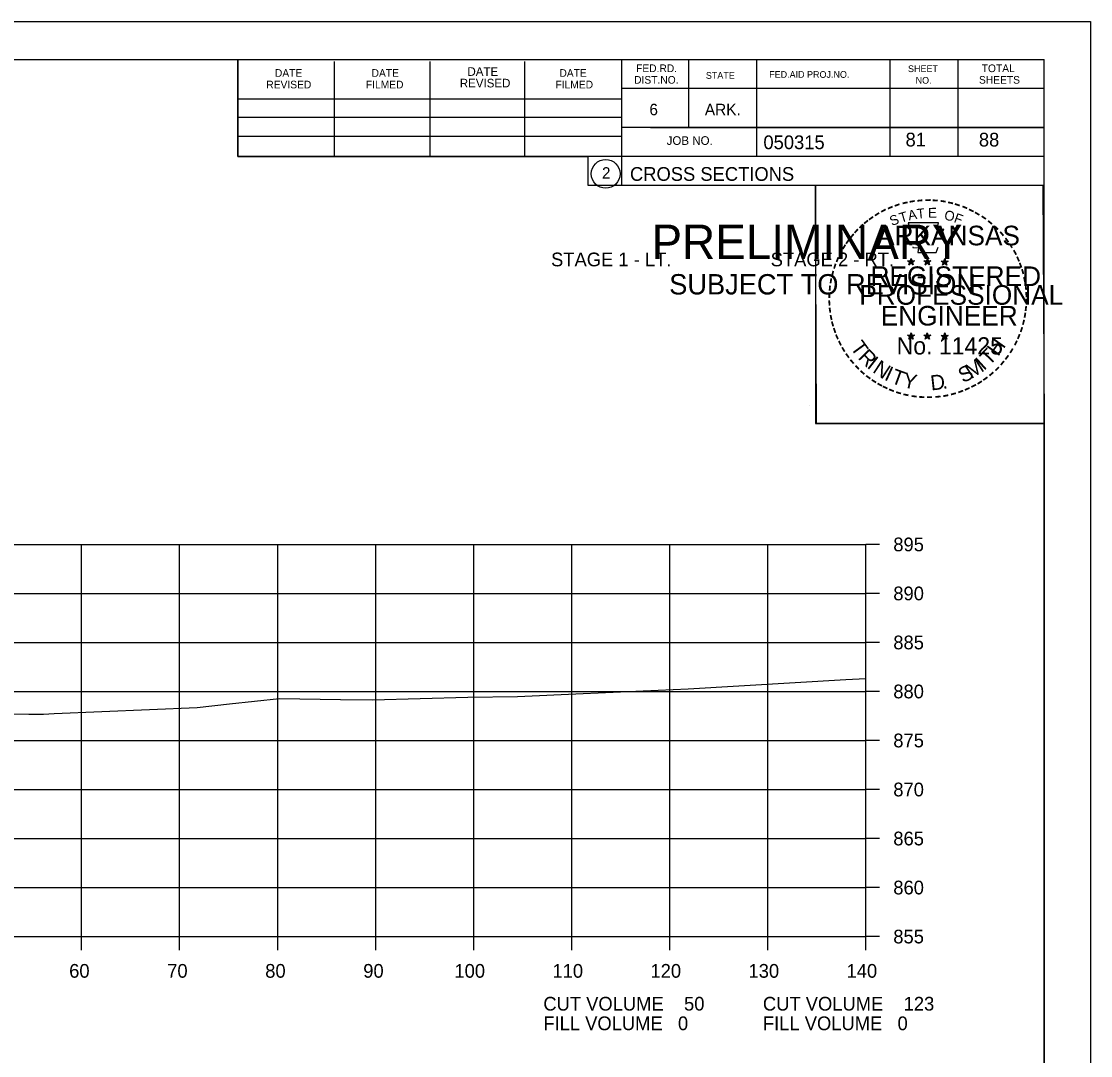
# Model space of a CAD drawing. Extents: x 1486524 to 1499135, y 326561 to 337924.
# Drawn here: x 1489036.7 to 1489145.8, y 334807.2 to 334912.7 of the extents above; entities that cross this region are included whole.
import ezdxf

# ---------------------------------------------------------------- set-up
doc = ezdxf.new("R2010")
doc.units = 0
for name, color, linetype in [('Default', 7, 'Continuous'), ('E_Const Align', 7, 'Continuous'), ('E_Const Align Station', 7, 'Continuous'), ('E_Ownership Information', 7, 'Continuous'), ('E_Property Line', 7, 'Continuous'), ('E_Quarter Calls', 7, 'Continuous'), ('E_Section Line', 7, 'Continuous'), ('E_Station Offset', 7, 'Continuous'), ('E_Tract Number', 7, 'Continuous'), ('S_SIXTEEN_SECTION', 7, 'Continuous')]:
    doc.layers.add(name, color=color, linetype=linetype)

msp = doc.modelspace()

# ---------------------------------------------------------------- linework, layer by layer
at = {"layer": 'E_Const Align'}
for p, q in [((1489122.89, 334819.33), (1489122.89, 334859.33)), ((1489124.29, 334859.33), (1489122.89, 334859.33)), ((1489124.29, 334854.33), (1489122.89, 334854.33)), ((1489124.29, 334849.33), (1489122.89, 334849.33)), ((1489124.29, 334844.33), (1489122.89, 334844.33)), ((1489124.29, 334839.33), (1489122.89, 334839.33)), ((1489124.29, 334834.33), (1489122.89, 334834.33)), ((1489124.29, 334829.33), (1489122.89, 334829.33)), ((1489124.29, 334824.33), (1489122.89, 334824.33)), ((1488842.89, 334819.33), (1489122.89, 334819.33)), ((1489042.89, 334817.93), (1489042.89, 334819.33)), ((1489052.89, 334817.93), (1489052.89, 334819.33)), ((1489062.89, 334817.93), (1489062.89, 334819.33)), ((1489072.89, 334817.93), (1489072.89, 334819.33)), ((1489082.89, 334817.93), (1489082.89, 334819.33)), ((1489092.89, 334817.93), (1489092.89, 334819.33)), ((1489102.89, 334817.93), (1489102.89, 334819.33)), ((1489112.89, 334817.93), (1489112.89, 334819.33)), ((1489122.89, 334817.93), (1489122.89, 334819.33)), ((1489124.29, 334819.33), (1489122.89, 334819.33))]:
    msp.add_line(p, q, dxfattribs=at)
at = {"layer": 'E_Ownership Information'}
for p, q in [((1488842.89, 334859.33), (1489122.89, 334859.33)), ((1489042.89, 334819.33), (1489042.89, 334859.33)), ((1489052.89, 334819.33), (1489052.89, 334859.33)), ((1489062.89, 334819.33), (1489062.89, 334859.33)), ((1489072.89, 334819.33), (1489072.89, 334859.33)), ((1489082.89, 334819.33), (1489082.89, 334859.33)), ((1489092.89, 334819.33), (1489092.89, 334859.33)), ((1489102.89, 334819.33), (1489102.89, 334859.33)), ((1489112.89, 334819.33), (1489112.89, 334859.33)), ((1489122.89, 334819.33), (1489122.89, 334859.33)), ((1488842.89, 334854.33), (1489122.89, 334854.33)), ((1488842.89, 334849.33), (1489122.89, 334849.33)), ((1488842.89, 334844.33), (1489122.89, 334844.33)), ((1488842.89, 334839.33), (1489122.89, 334839.33)), ((1488842.89, 334834.33), (1489122.89, 334834.33)), ((1488842.89, 334829.33), (1489122.89, 334829.33)), ((1488842.89, 334824.33), (1489122.89, 334824.33)), ((1488842.89, 334819.33), (1489122.89, 334819.33))]:
    msp.add_line(p, q, dxfattribs=at)
at = {"layer": 'E_Property Line'}
for p, q in [((1488824.89, 334908.79), (1489141.07, 334908.79)), ((1489058.81, 334898.91), (1489058.81, 334908.79)), ((1489068.67, 334898.91), (1489068.67, 334908.59)), ((1489078.43, 334898.91), (1489078.43, 334908.59)), ((1489088.11, 334898.91), (1489088.11, 334908.59)), ((1489097.97, 334908.79), (1489097.97, 334895.99)), ((1489104.81, 334908.79), (1489104.81, 334901.85)), ((1489111.75, 334908.79), (1489111.75, 334898.91)), ((1489125.33, 334908.79), (1489125.33, 334898.91)), ((1489132.27, 334908.79), (1489132.27, 334898.91)), ((1489141.07, 334703.33), (1489141.07, 334908.79)), ((1489141.07, 334905.85), (1489097.97, 334905.85)), ((1489141.07, 334905.87), (1489141.07, 334905.87)), ((1489058.81, 334904.77), (1489097.97, 334904.77)), ((1489058.81, 334902.91), (1489097.97, 334902.91)), ((1489141.07, 334901.85), (1489097.97, 334901.85)), ((1489100.93, 334901.85), (1489141.07, 334901.85)), ((1489058.81, 334898.91), (1489058.81, 334900.97)), ((1489058.81, 334900.97), (1489097.97, 334900.97)), ((1489141.07, 334898.91), (1489058.81, 334898.91)), ((1489097.97, 334895.99), (1489141.07, 334895.99))]:
    msp.add_line(p, q, dxfattribs=at)
msp.add_circle((1489096.35, 334897.13), 1.47, dxfattribs=at)
at = {"layer": 'E_Quarter Calls'}
for p, q in [((1488812.48, 334912.69), (1489145.82, 334912.69)), ((1489117.1, 334873.54), (1489117.1, 334873.54))]:
    msp.add_line(p, q, dxfattribs=at)
for points in [[(1488812.48, 334912.69), (1489145.82, 334912.69), (1489145.82, 334699.35), (1488812.48, 334699.35)], [(1489058.81, 334908.79), (1489058.81, 334898.91), (1489094.54, 334898.91), (1489094.54, 334895.99), (1489117.74, 334895.99), (1489117.74, 334871.66), (1489141.07, 334871.66), (1489141.07, 334703.33), (1488824.89, 334703.33), (1488824.89, 334908.79)], [(1489117.74, 334895.99), (1489140.94, 334895.99), (1489141.07, 334871.66), (1489117.86, 334871.66)]]:
    msp.add_lwpolyline(points, close=True, dxfattribs=at)
at = {"layer": 'E_Tract Number'}
msp.add_lwpolyline([(1489027.66, 334842.05), (1489037.52, 334842.02), (1489039.01, 334842.01), (1489040.08, 334842.07), (1489054.69, 334842.7), (1489057.97, 334843.07), (1489063.08, 334843.62), (1489069.29, 334843.52), (1489072.57, 334843.49), (1489082.3, 334843.74), (1489087.36, 334843.83), (1489094.07, 334844.13), (1489104.78, 334844.6), (1489120.86, 334845.55), (1489122.89, 334845.67)], dxfattribs=at)
at = {"layer": 'S_SIXTEEN_SECTION'}
for p, q in [((1489127.15, 334888.25), (1489127.5, 334888.14)), ((1489127.15, 334888.25), (1489127.4, 334888.2)), ((1489127.15, 334888.25), (1489127.39, 334888.12)), ((1489127.5, 334888.5), (1489127.46, 334888.25)), ((1489127.5, 334888.14), (1489127.5, 334888.5)), ((1489127.5, 334888.5), (1489127.55, 334888.25)), ((1489127.85, 334888.25), (1489127.5, 334888.14)), ((1489127.85, 334888.25), (1489127.56, 334888.2)), ((1489127.85, 334888.25), (1489127.64, 334888.14)), ((1489128.82, 334888.25), (1489129.17, 334888.14)), ((1489128.82, 334888.25), (1489129.07, 334888.2)), ((1489128.82, 334888.25), (1489129.06, 334888.12)), ((1489129.17, 334888.5), (1489129.13, 334888.25)), ((1489129.17, 334888.14), (1489129.17, 334888.5)), ((1489129.17, 334888.5), (1489129.22, 334888.25)), ((1489129.52, 334888.25), (1489129.17, 334888.14)), ((1489129.52, 334888.25), (1489129.23, 334888.2)), ((1489129.52, 334888.25), (1489129.31, 334888.14)), ((1489130.93, 334888.49), (1489130.89, 334888.24)), ((1489130.93, 334888.12), (1489130.93, 334888.49)), ((1489130.93, 334888.49), (1489130.98, 334888.24)), ((1489127.28, 334887.84), (1489127.5, 334888.14)), ((1489127.28, 334887.84), (1489127.41, 334888.08)), ((1489127.28, 334887.84), (1489127.5, 334888.06)), ((1489127.71, 334887.84), (1489127.5, 334888.14)), ((1489127.71, 334887.84), (1489127.5, 334888.05)), ((1489127.71, 334887.84), (1489127.58, 334888.13)), ((1489128.95, 334887.84), (1489129.17, 334888.14)), ((1489128.95, 334887.84), (1489129.08, 334888.08)), ((1489128.95, 334887.84), (1489129.17, 334888.06)), ((1489129.38, 334887.84), (1489129.17, 334888.14)), ((1489129.38, 334887.84), (1489129.17, 334888.05)), ((1489129.38, 334887.84), (1489129.25, 334888.13)), ((1489130.58, 334888.23), (1489130.93, 334888.12)), ((1489130.58, 334888.23), (1489130.84, 334888.19)), ((1489130.58, 334888.23), (1489130.82, 334888.11)), ((1489130.72, 334887.83), (1489130.93, 334888.12)), ((1489130.72, 334887.83), (1489130.84, 334888.07)), ((1489130.72, 334887.83), (1489130.93, 334888.04)), ((1489131.28, 334888.23), (1489130.93, 334888.12)), ((1489131.15, 334887.83), (1489130.93, 334888.12)), ((1489131.15, 334887.83), (1489130.93, 334888.04)), ((1489131.28, 334888.23), (1489130.99, 334888.19)), ((1489131.15, 334887.83), (1489131.01, 334888.12)), ((1489131.28, 334888.23), (1489131.08, 334888.13)), ((1489127.15, 334880.67), (1489127.5, 334880.56)), ((1489127.15, 334880.67), (1489127.4, 334880.63)), ((1489127.15, 334880.67), (1489127.38, 334880.55)), ((1489127.5, 334880.93), (1489127.45, 334880.68)), ((1489127.5, 334880.56), (1489127.5, 334880.93)), ((1489127.5, 334880.93), (1489127.54, 334880.68)), ((1489127.84, 334880.67), (1489127.5, 334880.56)), ((1489127.84, 334880.67), (1489127.56, 334880.62)), ((1489127.84, 334880.67), (1489127.64, 334880.57)), ((1489128.82, 334880.67), (1489129.16, 334880.56)), ((1489128.82, 334880.67), (1489129.07, 334880.63)), ((1489128.82, 334880.67), (1489129.05, 334880.55)), ((1489129.16, 334880.93), (1489129.12, 334880.68)), ((1489129.16, 334880.56), (1489129.16, 334880.93)), ((1489129.16, 334880.93), (1489129.21, 334880.68)), ((1489129.51, 334880.67), (1489129.16, 334880.56)), ((1489129.51, 334880.67), (1489129.23, 334880.62)), ((1489129.51, 334880.67), (1489129.31, 334880.57)), ((1489130.58, 334880.66), (1489130.93, 334880.55)), ((1489130.58, 334880.66), (1489130.84, 334880.62)), ((1489130.58, 334880.66), (1489130.82, 334880.54)), ((1489130.93, 334880.92), (1489130.89, 334880.67)), ((1489130.93, 334880.55), (1489130.93, 334880.92)), ((1489130.93, 334880.92), (1489130.98, 334880.67)), ((1489131.28, 334880.66), (1489130.93, 334880.55)), ((1489131.28, 334880.66), (1489130.99, 334880.61)), ((1489131.28, 334880.66), (1489131.07, 334880.56)), ((1489127.28, 334880.27), (1489127.5, 334880.56)), ((1489127.28, 334880.27), (1489127.41, 334880.51)), ((1489127.28, 334880.27), (1489127.49, 334880.48)), ((1489127.71, 334880.27), (1489127.49, 334880.48)), ((1489127.71, 334880.27), (1489127.5, 334880.56)), ((1489127.71, 334880.27), (1489127.57, 334880.56)), ((1489128.95, 334880.27), (1489129.16, 334880.56)), ((1489128.95, 334880.27), (1489129.07, 334880.51)), ((1489128.95, 334880.27), (1489129.16, 334880.48)), ((1489129.38, 334880.27), (1489129.16, 334880.56)), ((1489129.38, 334880.27), (1489129.16, 334880.48)), ((1489129.38, 334880.27), (1489129.24, 334880.56)), ((1489130.72, 334880.26), (1489130.93, 334880.55)), ((1489130.72, 334880.26), (1489130.84, 334880.5)), ((1489130.72, 334880.26), (1489130.93, 334880.47)), ((1489131.14, 334880.26), (1489130.93, 334880.55)), ((1489131.14, 334880.26), (1489130.93, 334880.47)), ((1489131.14, 334880.26), (1489131.01, 334880.55))]:
    msp.add_line(p, q, dxfattribs=at)
for points in [[(1489127.19, 334892.12), (1489127.46, 334891.3)], [(1489130.7, 334891.2), (1489130.84, 334891.49), (1489130.16, 334891.46), (1489130.31, 334892.12), (1489127.19, 334892.12)], [(1489127.68, 334889.7), (1489127.68, 334889.61), (1489128.25, 334889.6), (1489128.19, 334889.12), (1489130.06, 334889.12), (1489130.26, 334889.66)], [(1489127.5, 334888.5), (1489127.71, 334887.84), (1489127.15, 334888.25), (1489127.85, 334888.25), (1489127.28, 334887.84), (1489127.5, 334888.5)], [(1489129.17, 334888.5), (1489129.38, 334887.84), (1489128.82, 334888.25), (1489129.52, 334888.25), (1489128.95, 334887.84), (1489129.17, 334888.5)], [(1489130.93, 334888.49), (1489131.15, 334887.83), (1489130.58, 334888.23), (1489131.28, 334888.23), (1489130.72, 334887.83), (1489130.93, 334888.49)], [(1489127.5, 334880.93), (1489127.71, 334880.27), (1489127.15, 334880.67), (1489127.84, 334880.67), (1489127.28, 334880.27), (1489127.5, 334880.93)], [(1489129.16, 334880.93), (1489129.38, 334880.27), (1489128.82, 334880.67), (1489129.51, 334880.67), (1489128.95, 334880.27), (1489129.16, 334880.93)], [(1489130.93, 334880.92), (1489131.14, 334880.26), (1489130.58, 334880.66), (1489131.28, 334880.66), (1489130.72, 334880.26), (1489130.93, 334880.92)]]:
    msp.add_lwpolyline(points, dxfattribs=at)
for centre, radius in [((1489127.5, 334888.13), 0.172), ((1489127.5, 334888.13), 0.145), ((1489127.5, 334888.13), 0.116), ((1489129.17, 334888.13), 0.172), ((1489129.17, 334888.13), 0.145), ((1489129.17, 334888.13), 0.116), ((1489130.93, 334888.12), 0.172), ((1489130.93, 334888.12), 0.145), ((1489127.5, 334888.13), 0.0991), ((1489127.5, 334888.13), 0.0747), ((1489127.5, 334888.13), 0.0495), ((1489127.5, 334888.13), 0.0296), ((1489129.17, 334888.13), 0.0991), ((1489129.17, 334888.13), 0.0747), ((1489129.17, 334888.13), 0.0495), ((1489129.17, 334888.13), 0.0296), ((1489130.93, 334888.12), 0.116), ((1489130.93, 334888.12), 0.0991), ((1489130.93, 334888.12), 0.0747), ((1489130.93, 334888.12), 0.0495), ((1489130.93, 334888.12), 0.0296), ((1489127.49, 334880.56), 0.172), ((1489127.49, 334880.56), 0.145), ((1489127.49, 334880.56), 0.116), ((1489127.49, 334880.56), 0.0991), ((1489127.49, 334880.56), 0.0747), ((1489127.49, 334880.56), 0.0495), ((1489129.16, 334880.56), 0.172), ((1489129.16, 334880.56), 0.145), ((1489129.16, 334880.56), 0.116), ((1489129.16, 334880.56), 0.0991), ((1489129.16, 334880.56), 0.0747), ((1489129.16, 334880.56), 0.0495), ((1489130.93, 334880.55), 0.172), ((1489130.93, 334880.55), 0.145), ((1489130.93, 334880.55), 0.116), ((1489130.93, 334880.55), 0.0991), ((1489130.93, 334880.55), 0.0747), ((1489127.49, 334880.56), 0.0296), ((1489129.16, 334880.56), 0.0296), ((1489130.93, 334880.55), 0.0495), ((1489130.93, 334880.55), 0.0296)]:
    msp.add_circle(centre, radius, dxfattribs=at)

# ---------------------------------------------------------------- texts
at = {"layer": 'Default'}
for s, p in [('STAGE 1 - LT.', (1489090.78, 334887.7)), ('STAGE 2 - RT.', (1489113.18, 334887.7))]:
    msp.add_text(s, height=1.4, dxfattribs=at).set_placement(p)
at = {"layer": 'E_Const Align Station'}
for s, p in [('895', (1489125.69, 334858.63)), ('890', (1489125.69, 334853.63)), ('885', (1489125.69, 334848.63)), ('880', (1489125.69, 334843.63)), ('875', (1489125.69, 334838.63)), ('870', (1489125.69, 334833.63)), ('865', (1489125.69, 334828.63)), ('860', (1489125.69, 334823.63)), ('855', (1489125.69, 334818.63)), ('60', (1489041.62, 334815.13)), ('70', (1489051.62, 334815.13)), ('80', (1489061.62, 334815.13)), ('90', (1489071.62, 334815.13)), ('100', (1489080.92, 334815.13)), ('110', (1489090.92, 334815.13)), ('120', (1489100.92, 334815.13)), ('130', (1489110.92, 334815.13)), ('140', (1489120.92, 334815.13)), ('CUT VOLUME    50', (1489089.99, 334811.78)), ('CUT VOLUME    123', (1489112.39, 334811.78)), ('FILL VOLUME   0', (1489089.99, 334809.78)), ('FILL VOLUME   0', (1489112.39, 334809.78))]:
    msp.add_text(s, height=1.4, dxfattribs=at).set_placement(p)
at = {"layer": 'E_Property Line'}
for s, height, p in [('DATE', 0.879, (1489082.25, 334907.13)), ('FED.RD.', 0.782, (1489099.45, 334907.51)), ('SHEET', 0.684, (1489127.19, 334907.51)), ('TOTAL', 0.782, (1489134.71, 334907.51)), ('DATE', 0.782, (1489062.61, 334907.03)), ('DATE', 0.782, (1489072.47, 334907.03)), ('REVISED', 0.879, (1489081.47, 334905.95)), ('DATE', 0.782, (1489091.63, 334907.03)), ('DIST.NO.', 0.782, (1489099.25, 334906.33)), ('STATE', 0.684, (1489106.57, 334906.83)), ('FED.AID PROJ.NO.', 0.684, (1489113.03, 334906.93)), ('NO.', 0.684, (1489127.97, 334906.33)), ('SHEETS', 0.782, (1489134.43, 334906.33)), ('REVISED', 0.782, (1489061.73, 334905.85)), ('FILMED', 0.782, (1489071.89, 334905.85)), ('FILMED', 0.782, (1489091.23, 334905.85)), ('6', 1.17, (1489100.81, 334903.11)), ('ARK.', 1.172, (1489106.47, 334903.11)), ('JOB NO.', 0.879, (1489102.57, 334900.09)), ('050315', 1.4, (1489112.44, 334899.65)), ('2', 1.17, (1489095.97, 334896.64)), ('CROSS SECTIONS', 1.4, (1489098.83, 334896.42))]:
    msp.add_text(s, height=height, rotation=360, dxfattribs=at).set_placement(p)
at = {"layer": 'E_Section Line'}
for s, height, p in [('PRELIMINARY', 3.5, (1489101.02, 334888.45)), ('DWB', 0.01, (1489101.76, 334890.3)), ('SUBJECT TO REVISION', 2.0751, (1489102.83, 334884.83))]:
    msp.add_text(s, height=height, rotation=360, dxfattribs=at).set_placement(p)
at = {"layer": 'E_Station Offset'}
for s, p in [('81', (1489126.94, 334899.93)), ('88', (1489134.42, 334899.92))]:
    msp.add_text(s, height=1.4, dxfattribs=at).set_placement(p)
at = {"layer": 'S_SIXTEEN_SECTION'}
for s, height, rotation, p in [('-', 1.6, 24.3072, (1489125.31, 334892.98)), ('-', 1.6, 19.1761, (1489125.94, 334893.25)), ('-', 1.6, 13.6301, (1489126.69, 334893.49)), ('-', 1.6, 10.2193, (1489127.37, 334893.65)), ('-', 1.6, 5.8968, (1489128.1, 334893.76)), ('-', 1.6, 0.1862, (1489128.87, 334893.84)), ('-', 1.6, 357.743, (1489129.59, 334893.82)), ('-', 1.6, 352.1617, (1489130.34, 334893.77)), ('-', 1.6, 347.2049, (1489131.05, 334893.65)), ('-', 1.6, 342.3362, (1489131.69, 334893.5)), ('-', 1.6, 337.8551, (1489132.42, 334893.28)), ('-', 1.6, 36.2317, (1489123.5, 334891.9)), ('-', 1.6, 34.0636, (1489124.08, 334892.3)), ('-', 1.6, 28.7918, (1489124.67, 334892.67)), ('S', 1, 21.594, (1489125.55, 334891.8)), ('T', 1, 16.4036, (1489126.46, 334892.13)), ('A', 1, 11.2132, (1489127.29, 334892.38)), ('T', 1, 6.0228, (1489128.14, 334892.55)), ('E', 1, 0.8323, (1489129.24, 334892.66)), ('O', 1, 350.4515, (1489130.84, 334892.45)), ('F', 1, 340.0707, (1489131.8, 334892.22)), ('-', 1.6, 334.1211, (1489133.06, 334893)), ('-', 1.6, 329.6409, (1489133.63, 334892.72)), ('-', 1.6, 325.8627, (1489134.28, 334892.36)), ('-', 1.6, 48.423, (1489122.14, 334890.63)), ('-', 1.6, 42.9622, (1489122.59, 334891.11)), ('-', 1.6, 38.9507, (1489123.02, 334891.52)), ('ARKANSAS', 2, 360, (1489124.04, 334889.84)), ('-', 1.6, 320.5297, (1489134.89, 334891.93)), ('-', 1.6, 315.5786, (1489135.49, 334891.45)), ('-', 1.6, 54.2325, (1489121.32, 334889.57)), ('-', 1.6, 50.6142, (1489121.74, 334890.14)), ('-', 1.6, 309.8797, (1489136.06, 334890.9)), ('-', 1.6, 306.6522, (1489136.58, 334890.29)), ('-', 1.6, 58.0706, (1489121, 334889.05)), ('-', 1.4, 303.6753, (1489137.07, 334889.73)), ('-', 1.6, 299.6684, (1489137.39, 334889.12)), ('-', 1.6, 67.7743, (1489120.43, 334887.82)), ('-', 1.6, 62.8713, (1489120.69, 334888.43)), ('-', 1.6, 294.6628, (1489137.71, 334888.51)), ('-', 1.6, 75.461, (1489120.01, 334886.48)), ('-', 1.6, 72.3945, (1489120.21, 334887.19)), ('REGISTERED', 2, 360, (1489123.37, 334885.69)), ('DWB', 0.01, 360, (1489127.49, 334888.13)), ('DWB', 0.01, 360, (1489129.16, 334888.13)), ('DWB', 0.01, 360, (1489130.92, 334888.12)), ('-', 1.6, 290.5728, (1489137.97, 334887.93)), ('-', 1.6, 285.1233, (1489138.2, 334887.35)), ('-', 1.6, 81.2013, (1489119.88, 334885.77)), ('-', 1.6, 280.5493, (1489138.4, 334886.61)), ('-', 1.6, 89.0622, (1489119.78, 334884.37)), ('-', 1.6, 85.1863, (1489119.8, 334885.07)), ('PROFESSIONAL', 2, 360, (1489122.22, 334883.78)), ('-', 1.6, 276.5962, (1489138.56, 334885.84)), ('-', 1.6, 274.3301, (1489138.62, 334885.12)), ('-', 1.6, 94.1959, (1489119.81, 334883.65)), ('-', 1.6, 269.9407, (1489138.66, 334884.49)), ('-', 1.6, 98.9479, (1489119.89, 334882.98)), ('ENGINEER', 2, 360, (1489124.41, 334881.66)), ('-', 1.6, 260.9953, (1489138.57, 334883.17)), ('-', 1.6, 263.5172, (1489138.64, 334883.82)), ('-', 1.6, 101.7149, (1489120.02, 334882.25)), ('-', 1.6, 105.4578, (1489120.18, 334881.65)), ('-', 1.6, 255.7626, (1489138.46, 334882.49)), ('-', 1.6, 109.0874, (1489120.4, 334881.02)), ('-', 1.6, 114.0643, (1489120.65, 334880.43)), ('-', 1.6, 247.8887, (1489138.05, 334881.1)), ('-', 1.6, 252.8681, (1489138.28, 334881.77)), ('-', 1.6, 115.7289, (1489120.96, 334879.81)), ('T', 1.54, 306.0406, (1489121.25, 334879.4)), ('No. 11425', 1.757, 360, (1489126.03, 334878.71)), ('DWB', 0.01, 360, (1489127.48, 334880.56)), ('DWB', 0.01, 360, (1489129.15, 334880.56)), ('DWB', 0.01, 360, (1489130.92, 334880.55)), ('H', 1.54, 54.6088, (1489136.38, 334878.44)), ('-', 1.6, 244.6197, (1489137.79, 334880.47)), ('-', 1.6, 120.4471, (1489121.31, 334879.22)), ('-', 1.6, 125.8934, (1489121.72, 334878.66)), ('R', 1.54, 314.005, (1489122.02, 334878.35)), ('I', 1.54, 321.9694, (1489122.92, 334877.42)), ('T', 1.54, 46.6444, (1489135.49, 334877.49)), ('-', 1.6, 233.8452, (1489136.99, 334879.06)), ('-', 1.6, 239.0712, (1489137.4, 334879.71)), ('-', 1.6, 130.7181, (1489122.18, 334878.11)), ('-', 1.6, 134.2238, (1489122.7, 334877.56)), ('N', 1.54, 326.5002, (1489123.49, 334876.95)), ('I', 1.54, 335.3603, (1489124.69, 334876.16)), ('S', 1.54, 26.9312, (1489132.8, 334875.76)), ('M', 1.54, 32.6563, (1489133.64, 334876.17)), ('I', 1.54, 42.1136, (1489134.92, 334877.01)), ('-', 1.6, 225.7653, (1489136.09, 334877.93)), ('-', 1.6, 231.2538, (1489136.56, 334878.5)), ('-', 1.6, 138.9338, (1489123.22, 334877.1)), ('-', 1.6, 144.6463, (1489123.78, 334876.69)), ('T', 1.54, 339.8912, (1489125.35, 334875.84)), ('Y', 1.54, 347.8556, (1489126.57, 334875.39)), ('D', 1.54, 6.3969, (1489129.56, 334875.03)), ('-', 1.6, 215.7363, (1489135.01, 334876.95)), ('-', 1.6, 221.0851, (1489135.56, 334877.42)), ('-', 1.6, 148.0898, (1489124.34, 334876.32)), ('-', 1.6, 151.5704, (1489124.92, 334876)), ('-', 1.6, 154.6002, (1489125.44, 334875.75)), ('-', 1.6, 158.5612, (1489126.06, 334875.5)), ('.', 1.54, 13.7642, (1489130.75, 334875.16)), ('-', 1.6, 204.2516, (1489133.3, 334875.9)), ('-', 1.6, 207.3568, (1489133.92, 334876.22)), ('-', 1.6, 212.2491, (1489134.48, 334876.56)), ('-', 1.6, 162.7983, (1489126.75, 334875.28)), ('-', 1.6, 167.5555, (1489127.46, 334875.12)), ('-', 1.6, 173.1155, (1489128.24, 334875.01)), ('-', 1.6, 176.5183, (1489128.98, 334874.96)), ('-', 1.6, 181.5918, (1489129.73, 334874.98)), ('-', 1.6, 185.8167, (1489130.54, 334875.05)), ('-', 1.6, 191.2858, (1489131.27, 334875.18)), ('-', 1.6, 195.4743, (1489132, 334875.38)), ('-', 1.6, 200.7184, (1489132.68, 334875.63))]:
    msp.add_text(s, height=height, rotation=rotation, dxfattribs=at).set_placement(p)

doc.saveas('drawing.dxf')
